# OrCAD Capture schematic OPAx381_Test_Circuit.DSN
size A; title: OPA381, Precision, Low Power, 18MHz Transimpedance Amplifier; rev: 1.1; note: Datasheet: SBOS313B EVM: N/A
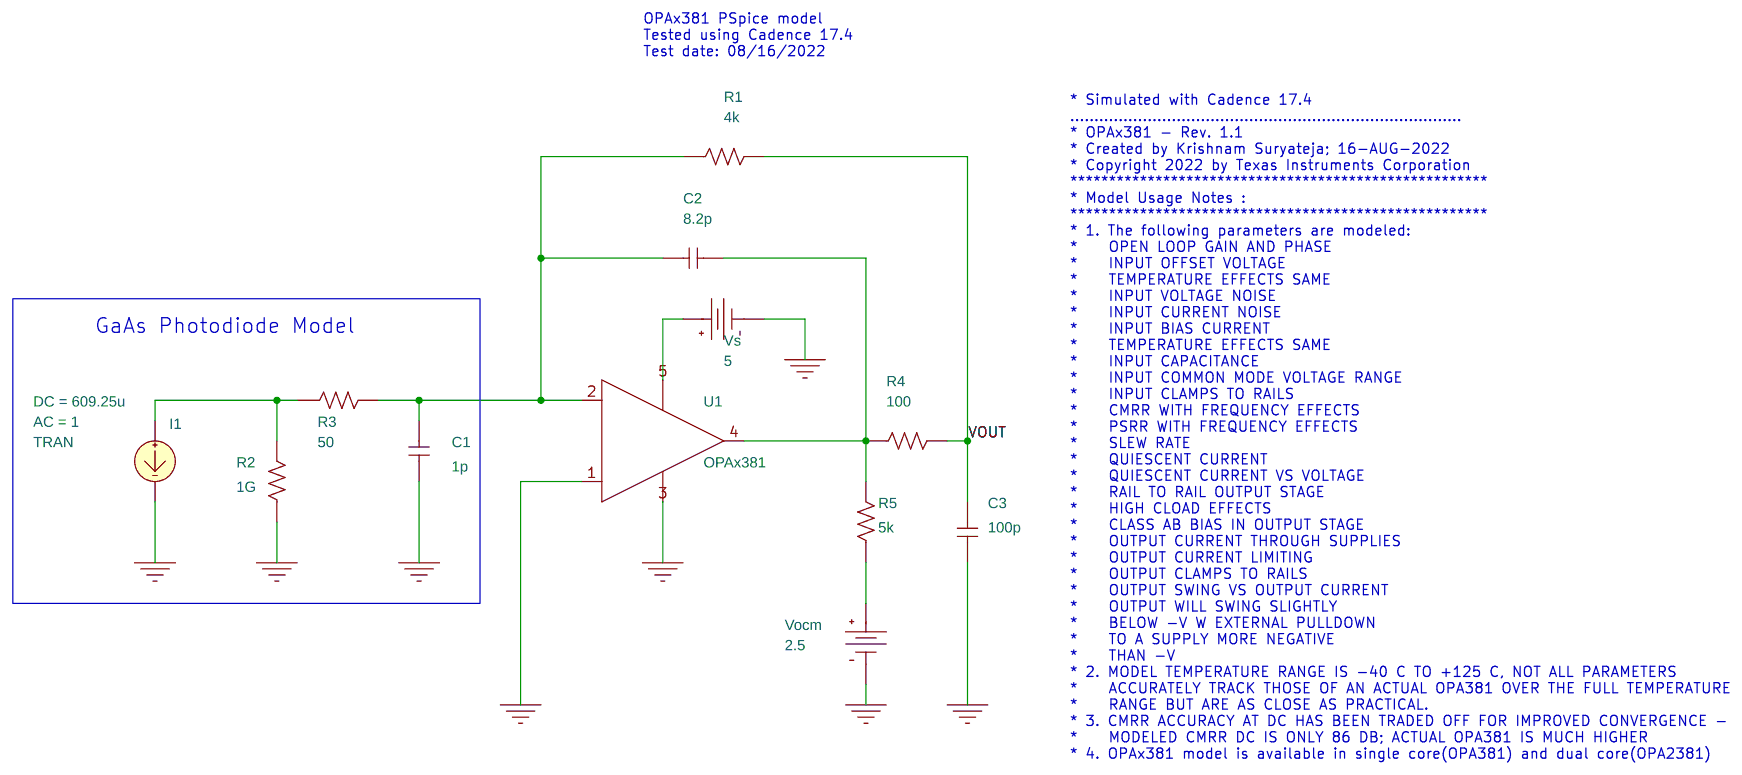
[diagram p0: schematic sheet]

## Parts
C1  1p  [RAD/CK05]
C2  8.2p  [RAD/CK05]
C3  100p  [RAD/CK05]
I1  ISRC
R1  4k  [AX/RC05]
R2  1G  [AX/RC05]
R3  50  [AX/RC05]
R4  100  [AX/RC05]
R5  5k  [AX/RC05]
U1  OPAx381
Vocm  VDC
Vs  VDC

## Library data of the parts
C1-C3 = C
I1 = ISRC: AC: 1; DC: 609.25u; TRAN: PWL  REPEAT FOREVER (0, 609.25u) (1p 809.25u) (999.9995n 809.25u) (1000.0005n 409.25u) (1999.999n 409.25u) (2u  609.25u) ENDREPEAT
R1-R5 = R
U1 = OPAx381
Vocm = VDC: DC: 2.5
Vs = VDC: DC: 5

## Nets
0: C1.1 C3.1 I1.2(-) R2.1 U1.1(+) U1.3(V-) Vocm.1(-) Vs.1(-)
VOUT: C3.2 R1.2 R4.2
N00481: C1.2 C2.1 R1.1 R3.2 U1.2(-)
N14293711: C2.2 R4.1 R5.2 U1.4(OUT)
N14294978: I1.1(+) R2.2 R3.1
N14307881: R5.1 Vocm.0(+)
N14310225: U1.5(V+) Vs.0(+)

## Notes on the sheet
- OPAx381 PSpice model
  Tested using Cadence 17.4
  Test date: 08/16/2022
- * Simulated with Cadence 17.4
  .................................................................................
  * OPAx381 - Rev. 1.1
  * Created by Krishnam Suryateja; 16-AUG-2022
  * Copyright 2022 by Texas Instruments Corporation
  ******************************************************
  * Model Usage Notes :
  ******************************************************
  * 1. The following parameters are modeled:
  *    OPEN LOOP GAIN AND PHASE
  *    INPUT OFFSET VOLTAGE
  *    TEMPERATURE EFFECTS SAME
  *    INPUT VOLTAGE NOISE
  *    INPUT CURRENT NOISE
  *    INPUT BIAS CURRENT
  *    TEMPERATURE EFFECTS SAME
  *    INPUT CAPACITANCE
  *    INPUT COMMON MODE VOLTAGE RANGE
  *    INPUT CLAMPS TO RAILS
  *    CMRR WITH FREQUENCY EFFECTS
  *    PSRR WITH FREQUENCY EFFECTS
  *    SLEW RATE
  *    QUIESCENT CURRENT
  *    QUIESCENT CURRENT VS VOLTAGE
  *    RAIL TO RAIL OUTPUT STAGE
  *    HIGH CLOAD EFFECTS
  *    CLASS AB BIAS IN OUTPUT STAGE
  *    OUTPUT CURRENT THROUGH SUPPLIES
  *    OUTPUT CURRENT LIMITING
  *    OUTPUT CLAMPS TO RAILS
  *    OUTPUT SWING VS OUTPUT CURRENT
  *    OUTPUT WILL SWING SLIGHTLY
  *    BELOW -V W EXTERNAL PULLDOWN
  *    TO A SUPPLY MORE NEGATIVE
  *    THAN -V
  * 2. MODEL TEMPERATURE RANGE IS -40 C TO +125 C, NOT ALL PARAMETERS
  *    ACCURATELY TRACK THOSE OF AN ACTUAL OPA381 OVER THE FULL TEMPERATURE
  *    RANGE BUT ARE AS CLOSE AS PRACTICAL.
  * 3. CMRR ACCURACY AT DC HAS BEEN TRADED OFF FOR IMPROVED CONVERGENCE -
  *    MODELED CMRR DC IS ONLY 86 DB; ACTUAL OPA381 IS MUCH HIGHER
  * 4. OPAx381 model is available in single core(OPA381) and dual core(OPA2381)
- GaAs Photodiode Model
